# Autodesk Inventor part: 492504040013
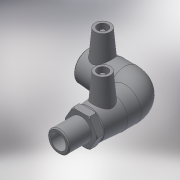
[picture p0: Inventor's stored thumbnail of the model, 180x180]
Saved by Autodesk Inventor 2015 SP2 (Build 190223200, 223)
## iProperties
Created: 2017-06
Part Number: 492504040013
Material: Generic
Description: PLASSON 90° ELBOW MALE TRANSITION 40-1.1/4"
Document SubType Name: Modeling
Designer: KIM
Mass: 202.965 g
Surface Area: 503.12 cm^2
Volume: 202.965 cm^3
Density: 1 g/cm^3
Appearance: Default
Author: KIM
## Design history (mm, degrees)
derived "492504.ipt"
feature "Solid1::492504.ipt"
tag "TaggingFeature1"
body "Solid1"
other parameters: "d2" = 56, "d4" = 30.66667, "d5" = 50.4, "d8" = 168 deg, "d10" = 17.6, "d11" = 5.86667, "d29" = 47, "d30" = 15, "d31" = 50.6, "d34" = 5 deg, "d41" = 4, "d42" = 14, "d43" = 0, "d48" = 64, "d50" = 34, "d51" = 17.6, "d52" = 44, "d54" = 90 deg, "d58" = 44, "d59" = 0, "d61" = 90 deg, "d86" = 3, "d87" = 0, "d93" = 0.1, "d94" = 9, "d95" = 41.91, "d96" = 29.337, "d97" = 29, "d98" = 36, "d99" = 56, "d100" = 32.4, "d102" = 2, "d106" = 0, "L_" = 128, "L_1" = 44, "D_" = 29, "A_" = 47, "d_2" = 12, "L_2" = 36, "D_1" = 56, "R_" = 41.91
